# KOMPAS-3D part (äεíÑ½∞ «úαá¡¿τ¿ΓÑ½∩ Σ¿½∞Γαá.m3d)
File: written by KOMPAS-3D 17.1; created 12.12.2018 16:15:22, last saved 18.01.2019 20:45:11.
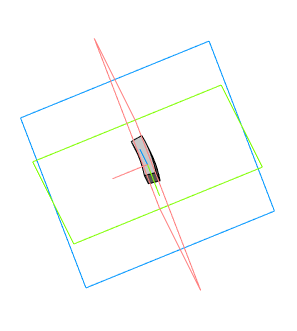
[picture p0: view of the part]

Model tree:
1. Эскиз:1
2. Операция выдавливания:1
     Расстояние 1 = 5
